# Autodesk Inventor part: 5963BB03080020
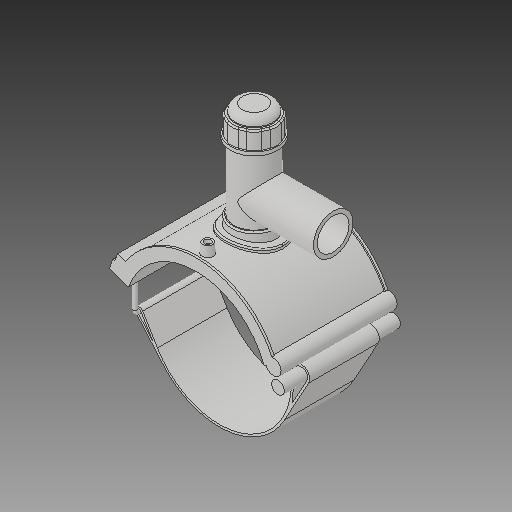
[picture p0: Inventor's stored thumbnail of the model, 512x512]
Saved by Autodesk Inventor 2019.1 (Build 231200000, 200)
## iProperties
Created: 2017-07
Part Number: 5963BB03080020
Material: Generic
Description: PLASSON TAPPING SADDLE 8''IPS x 2''IPS
Document SubType Name: Modeling
Designer: KIM
Mass: 1712.7 g
Surface Area: 2671.49 cm^2
Volume: 1712.7 cm^3
Density: 1 g/cm^3
Appearance: Default
Author: KIM
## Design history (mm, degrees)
derived "5963B.ipt"
feature "Solid1::5963B.ipt"
feature "Solid2::5963B.ipt"
feature "Solid4::5963B.ipt"
feature "Solid5::5963B.ipt"
tag "TaggingFeature1" dims "d0" = 218.7
body "Solid1"
body "Solid2"
other parameters: "d2" = 269.748, "d3" = 54.675, "d4" = 176.022, "d5" = 0, "d6" = 0.1, "d8" = 0, "d19" = 6, "d20" = 6, "d21" = 105.6132, "d23" = 0, "d24" = 52.8066, "d26" = 0, "d29" = 3, "d30" = 72.9, "d31" = 6, "d32" = 0, "d33" = 0, "d34" = 0.6, "d40" = 129.64536, "d41" = 87.48, "d43" = 0, "d45" = 0, "d47" = 230.2722, "d70" = 15, "d72" = 0, "d73" = 6, "d75" = 5, "d76" = 0, "d77" = 10.935, "d78" = 139.35, "d79" = 15, "d80" = 70.4088, "d82" = 5 deg, "d84" = 4, "d85" = 14, "d86" = 0, "d87" = 3, "d88" = 0, "d89" = 1, "d90" = 1, "d91" = 140.8176, "d92" = 0, "d93" = 0.5, "d94" = 115.10526, "d96" = 254.30436, "d97" = 3.52044, "d98" = 0, "d102" = 2.187, "d120" = 140 deg, "d121" = 24.228, "d122" = 20 deg, "d123" = 498.636, "d124" = 149.5908, "d126" = 0, "d143" = 225.261, "d145" = 23.55231, "d149" = 3.2805, "d150" = 25.90754, "d153" = 176.022, "d154" = 0, "d156" = 124.659, "d157" = 160 deg, "d159" = 6.1236, "d161" = 3.2805, "d162" = 105.6132, "d163" = 0, "d164" = 109.35, "d167" = 21.87, "d168" = 121.61854, "d170" = 3.2805, "d172" = 0, "d173" = 1, "d175" = 109.35, "d176" = 20 deg, "d177" = 15.309, "d178" = 30.618, "d180" = 0, "d183" = 12.2472, "d184" = 12.2472, "d185" = 57.20715, "d186" = 57.20715, "d187" = 124.659, "d188" = 9.1854, "d189" = 15.309, "d190" = 0, "d191" = 186.9885, "d193" = 6.1236, "d194" = 6.16077, "d195" = 90 deg, "d197" = 0, "d199" = 0, "d200" = 15.309, "d202" = 0, "d203" = 177.038, "d204" = 68.14692, "d205" = 50.21352, "d206" = 60.97356, "d207" = 132.7785, "d208" = 138.08964, "d209" = 164.64534, "d210" = 61.6909, "d211" = 71.7336, "d212" = 57.38688, "d213" = 31.4766, "d216" = 0, "d217" = 21.87, "d218" = 10.935, "d219" = 2.187, "d222" = 218.7, "d224" = 0, "d230" = 2.187, "d233" = 6, "d236" = 89.916, "d237" = 52.8066, "d238" = 6.02433, "d240" = 52.8066, "d241" = 52.8066, "d242" = 52.8066, "d243" = 6, "d244" = 52.8066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
